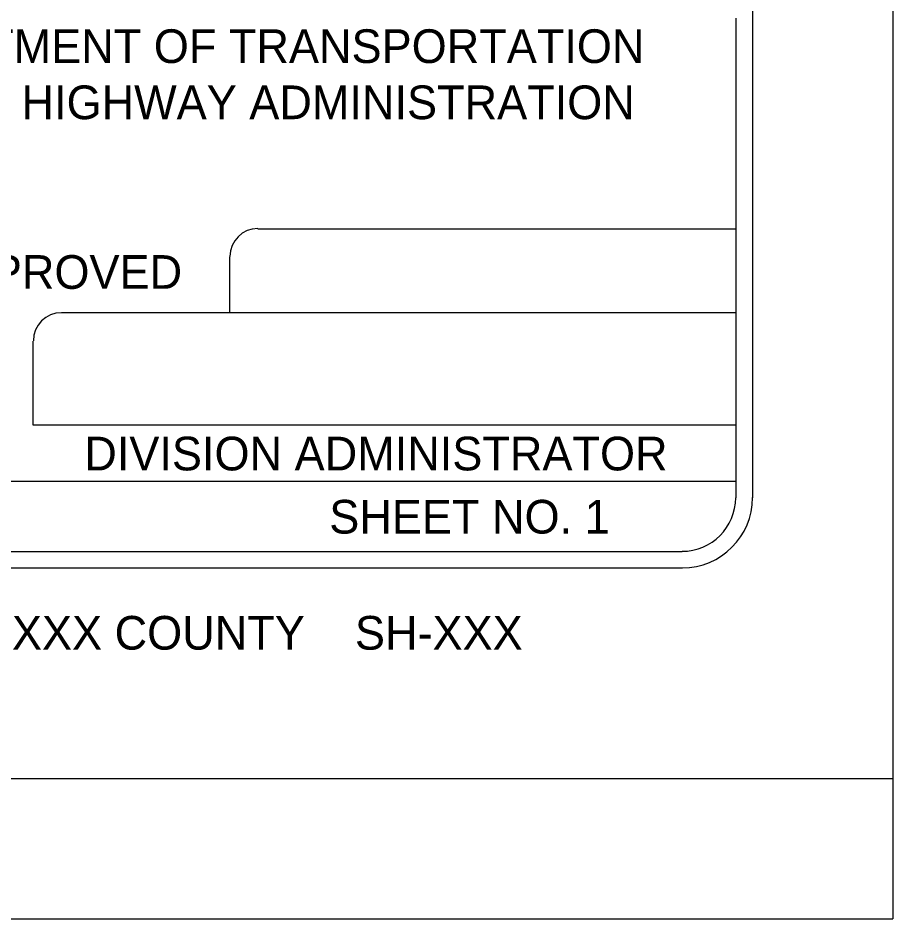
# Model space of a CAD drawing. Extents: x 1458004.1 to 1458040.9, y 194172.7 to 194198.1.
# Drawn here: x 1458036.944 to 1458040.06, y 194172.739 to 194175.948 of the extents above; entities that cross this region are included whole.
import ezdxf

# ---------------------------------------------------------------- set-up
doc = ezdxf.new("R2010")
doc.units = 0
for name, color, linetype in [('Border_0', 7, 'Continuous'), ('Border_9', 7, 'Continuous'), ('IPlot_Plot_Limits', 7, 'Continuous'), ('Text_0', 7, 'Continuous'), ('Text_Box_3', 7, 'Continuous'), ('Text_Box_4', 7, 'Continuous')]:
    doc.layers.add(name, color=color, linetype=linetype)

msp = doc.modelspace()

# ---------------------------------------------------------------- linework, layer by layer
at = {"layer": 'Border_0'}
msp.add_line((1458005.56, 194173.2392), (1458040.06, 194173.2392), dxfattribs=at)
at = {"layer": 'Border_9'}
for p, q in [((1458039.56, 194194.2392), (1458039.56, 194174.2392)), ((1458007.31, 194173.9892), (1458039.31, 194173.9892))]:
    msp.add_line(p, q, dxfattribs=at)
msp.add_arc((1458039.3098, 194174.2396), 0.25, 270, 0, dxfattribs=at)
at = {"layer": 'IPlot_Plot_Limits'}
for p in [(1458040.06, 194195.7392), (1458004.06, 194172.7392)]:
    msp.add_line(p, (1458040.06, 194172.7392), dxfattribs=at)
at = {"layer": 'Text_Box_3'}
for p, q in [((1458037.7983, 194175.1975), (1458039.5, 194175.1975)), ((1458037.6983, 194174.8975), (1458037.6983, 194175.0975)), ((1458039.5, 194174.8975), (1458037.0983, 194174.8975)), ((1458036.9983, 194174.4983), (1458036.9983, 194174.7975)), ((1458039.5, 194174.4983), (1458036.9983, 194174.4983))]:
    msp.add_line(p, q, dxfattribs=at)
for centre in [(1458037.7985, 194175.0983), (1458037.0987, 194174.7982)]:
    msp.add_arc(centre, 0.1, 90, 180, dxfattribs=at)
at = {"layer": 'Text_Box_4'}
for p, q in [((1458039.5, 194175.9475), (1458039.5, 194174.2392)), ((1458031.9967, 194174.2983), (1458039.5, 194174.2983)), ((1458031.9967, 194174.0483), (1458039.3092, 194174.0483))]:
    msp.add_line(p, q, dxfattribs=at)
msp.add_arc((1458039.309, 194174.2395), 0.1909, 270, 0, dxfattribs=at)

# ---------------------------------------------------------------- texts
at = {"layer": 'Text_0'}
for s, p in [('DEPARTMENT OF TRANSPORTATION', (1458036.2775, 194175.7875)), ('FEDERAL HIGHWAY ADMINISTRATION', (1458036.1717, 194175.5875)), ('DATE APPROVED', (1458036.1642, 194174.9833)), ('DIVISION ADMINISTRATOR', (1458037.18, 194174.3367)), ('SHEET NO. 1', (1458038.0525, 194174.1117)), ('XXXX COUNTY    SH-XXX', (1458036.8153, 194173.6983))]:
    msp.add_text(s, height=0.12, dxfattribs=at).set_placement(p)

doc.saveas('drawing.dxf')
